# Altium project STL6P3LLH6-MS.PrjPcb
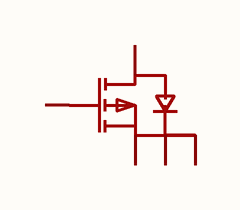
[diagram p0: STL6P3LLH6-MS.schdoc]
1 sheet, 1 parts. Net scope: global (net labels, ports and power ports of the same name join across sheets).

## Sheet STL6P3LLH6-MS.schdoc
size 127 x 101 mm

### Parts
Q?  stl6p3llh6-ms  [DFN-8_L3.3-W3.3-P0.65-BL]  (value not drawn)

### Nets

Not connected (* = marked no-connect by the designer): Q? 1(S) 2(S) 3(S) 4(G) 5(D)

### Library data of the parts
Q? = stl6p3llh6-ms: 数量:1个P沟道;漏源电压(Vdss):30V;连续漏极电流(Id):25A;导通电阻(RDS(on)):16mΩ@10V;耗散功率(Pd):29W;阈值电压(Vgs(th)):1V;; Manufacturer: MSKSEMI(美森科); AddInBom: yes; ModelId: f0059a17dd8f409ba5a4c367eb8306e1; ModelTransform: 129.921,129.99974,0,0,0,0,0.002,31.498,0; Number: 1个P沟道; Drain to Source Voltage: 30V; Current - Continuous Drain(Id): 25A; Pd - Power Dissipation: 29W; Gate Threshold Voltage (Vgs(th)): 1V; Gate Charge(Qg): 52nC; Input Capacitance(Ciss): 1.15nF; Reverse Transfer Capacitance (Crss@Vds): 134pF; Configuration: 独立式; Type: P沟道; Output Capacitance(Coss): 150pF; Vgs: ±20V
